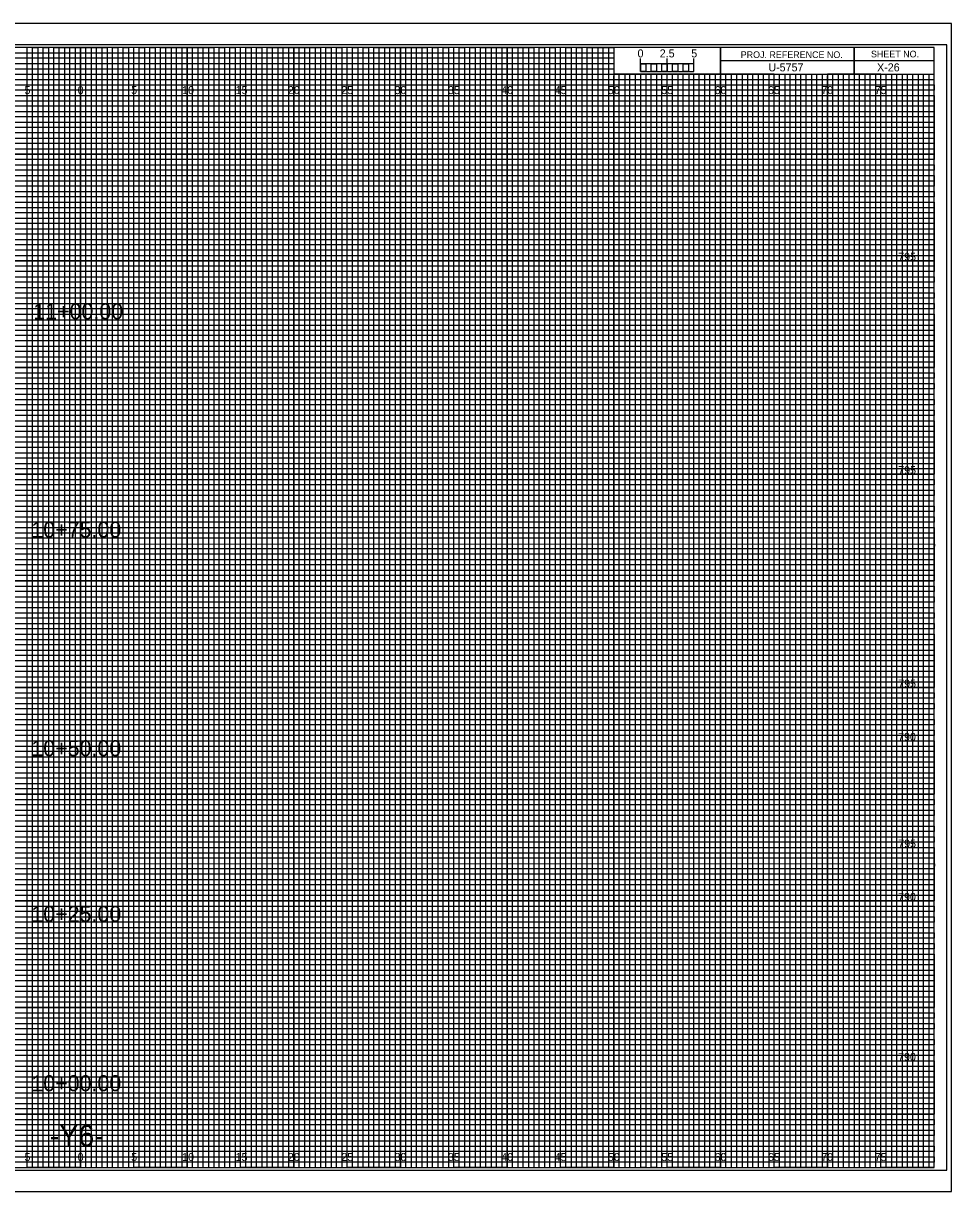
# Model space of a CAD drawing. Extents: x -7 to 162, y -2 to 107.
# Drawn here: x 74.6 to 161.7, y -2.3 to 107.3 of the extents above; entities that cross this region are included whole.
import ezdxf

# ---------------------------------------------------------------- set-up
doc = ezdxf.new("R2010")
doc.units = 0
for name, color, linetype in [('Exist Cross Section Cell', 7, 'Continuous'), ('Exist XS Center Line Elevation Label', 7, 'Continuous'), ('Prop CMT Pvmt Surface Shoulder', 7, 'Continuous'), ('Prop CMT Shld Paved Course 1', 7, 'Continuous'), ('Prop CMT Shld Paved Course 2', 7, 'Continuous'), ('Prop CMT Shld Paved Course 3', 7, 'Continuous'), ('Prop XS Alignment Label', 7, 'Continuous'), ('Prop XS Bar Scale Labels', 7, 'Continuous'), ('Prop XS Elevation Labels', 7, 'Continuous'), ('Prop XS Finish Grade CurbGutter', 7, 'Continuous'), ('Prop XS Hydro Elevations', 7, 'Continuous'), ('Prop XS Project Number', 7, 'Continuous'), ('Prop XS SE Text', 7, 'Continuous'), ('Prop XS Sheet Number', 7, 'Continuous'), ('Prop XS Side Slope Text', 7, 'Continuous'), ('Prop XS Station Labels', 7, 'Continuous'), ('Sheet DOT Grid CELL', 7, 'Continuous')]:
    doc.layers.add(name, color=color, linetype=linetype)

msp = doc.modelspace()

# ---------------------------------------------------------------- linework, layer by layer
at = {"layer": 'Exist Cross Section Cell'}
for p, q in [((75, 105), (70, 105)), ((75, 0), (75, 105)), ((85, 105), (80, 105)), ((80, 105), (80, 0)), ((85, 0), (85, 105)), ((95, 105), (90, 105)), ((90, 105), (90, 0)), ((95, 0), (95, 105)), ((105, 105), (100, 105)), ((100, 105), (100, 0)), ((105, 0), (105, 105)), ((115, 105), (110, 105)), ((110, 105), (110, 0)), ((115, 0), (115, 105)), ((125, 105), (120, 105)), ((120, 105), (120, 0)), ((125, 0), (125, 105)), ((130, 105), (130, 0)), ((135, 0), (135, 102.5)), ((145, 102.5), (140, 102.5)), ((140, 102.5), (140, 0)), ((145, 0), (145, 102.5)), ((155, 102.5), (150, 102.5)), ((150, 102.5), (150, 0)), ((155, 0), (155, 102.5)), ((80, 0), (75, 0)), ((90, 0), (85, 0)), ((100, 0), (95, 0)), ((110, 0), (105, 0)), ((120, 0), (115, 0)), ((130, 0), (125, 0)), ((140, 0), (135, 0)), ((150, 0), (145, 0)), ((160, 0), (155, 0)), ((160, 0), (160, 0))]:
    msp.add_line(p, q, dxfattribs=at)
for points in [[(0, 100), (160, 100), (160, 95), (0, 95)], [(0, 90), (160, 90), (160, 85), (0, 85)], [(0, 80), (160, 80), (160, 75), (0, 75)], [(0, 70), (160, 70), (160, 65), (0, 65)], [(0, 60), (160, 60), (160, 55), (0, 55)], [(0, 50), (160, 50), (160, 45), (0, 45)], [(0, 40), (160, 40), (160, 35), (0, 35)], [(0, 30), (160, 30), (160, 25), (0, 25)], [(0, 20), (160, 20), (160, 15), (0, 15)], [(0, 10), (160, 10), (160, 5), (0, 5)]]:
    msp.add_lwpolyline(points, dxfattribs=at)
at = {"layer": 'Exist XS Center Line Elevation Label'}
for points in [[(72.5, 0), (77.5, 0), (77.5, 105), (82.5, 105), (82.5, 0), (87.5, 0), (87.5, 105), (92.5, 105), (92.5, 0), (97.5, 0), (97.5, 105), (102.5, 105), (102.5, 0), (107.5, 0), (107.5, 105), (112.5, 105), (112.5, 0), (117.5, 0), (117.5, 105), (122.5, 105), (122.5, 0), (127.5, 0), (127.5, 105), (129.97, 105), (130, 105), (130, 102.5), (132.5, 102.5), (132.5, 0), (137.5, 0), (137.5, 102.5), (142.5, 102.5), (142.5, 0), (147.5, 0), (147.5, 102.5), (152.5, 102.5), (152.5, 0), (157.5, 0), (157.5, 102.5)], [(0, 102.5), (137.5, 102.5)], [(0, 92.5), (160, 92.5), (160, 97.5), (0, 97.5)], [(0, 82.5), (160, 82.5), (160, 87.5), (0, 87.5)], [(0, 72.5), (160, 72.5), (160, 77.5), (0, 77.5)], [(0, 62.5), (160, 62.5), (160, 67.5), (0, 67.5)], [(0, 52.5), (160, 52.5), (160, 57.5), (0, 57.5)], [(0, 42.5), (160, 42.5), (160, 47.5), (0, 47.5)], [(0, 32.5), (160, 32.5), (160, 37.5), (0, 37.5)], [(0, 22.5), (160, 22.5), (160, 27.5), (0, 27.5)], [(0, 12.5), (160, 12.5), (160, 17.5), (0, 17.5)], [(0, 2.5), (160, 2.5), (160, 7.5), (0, 7.5)]]:
    msp.add_lwpolyline(points, dxfattribs=at)
at = {"layer": 'Prop CMT Pvmt Surface Shoulder'}
msp.add_lwpolyline([(-5.4, -0.25), (161.2, -0.25), (161.2, 105.25), (-5.4, 105.25)], close=True, dxfattribs=at)
at = {"layer": 'Prop CMT Shld Paved Course 1'}
for p, q in [((133.5, 102.5), (133, 102.5)), ((133, 102.5), (133, 0)), ((133.5, 0), (133.5, 102.5)), ((134.5, 102.5), (134, 102.5)), ((134, 102.5), (134, 0)), ((134.5, 0), (134.5, 102.5)), ((133, 0), (132.5, 0)), ((134, 0), (133.5, 0))]:
    msp.add_line(p, q, dxfattribs=at)
for points in [[(75, 0), (75.5, 0), (75.5, 105), (76, 105), (76, 0)], [(76, 0), (76.5, 0), (76.5, 105), (77, 105), (77, 0)], [(77.5, 0), (78, 0), (78, 105), (78.5, 105), (78.5, 0)], [(78.5, 0), (79, 0), (79, 105), (79.5, 105), (79.5, 0)], [(80, 0), (80.5, 0), (80.5, 105), (81, 105), (81, 0)], [(81, 0), (81.5, 0), (81.5, 105), (82, 105), (82, 0)], [(82.5, 0), (83, 0), (83, 105), (83.5, 105), (83.5, 0)], [(83.5, 0), (84, 0), (84, 105), (84.5, 105), (84.5, 0)], [(85, 0), (85.5, 0), (85.5, 105), (86, 105), (86, 0)], [(86, 0), (86.5, 0), (86.5, 105), (87, 105), (87, 0)], [(87.5, 0), (88, 0), (88, 105), (88.5, 105), (88.5, 0)], [(88.5, 0), (89, 0), (89, 105), (89.5, 105), (89.5, 0)], [(90, 0), (90.5, 0), (90.5, 105), (91, 105), (91, 0)], [(91, 0), (91.5, 0), (91.5, 105), (92, 105), (92, 0)], [(92.5, 0), (93, 0), (93, 105), (93.5, 105), (93.5, 0)], [(93.5, 0), (94, 0), (94, 105), (94.5, 105), (94.5, 0)], [(95, 0), (95.5, 0), (95.5, 105), (96, 105), (96, 0)], [(96, 0), (96.5, 0), (96.5, 105), (97, 105), (97, 0)], [(97.5, 0), (98, 0), (98, 105), (98.5, 105), (98.5, 0)], [(98.5, 0), (99, 0), (99, 105), (99.5, 105), (99.5, 0)], [(100, 0), (100.5, 0), (100.5, 105), (101, 105), (101, 0)], [(101, 0), (101.5, 0), (101.5, 105), (102, 105), (102, 0)], [(102.5, 0), (103, 0), (103, 105), (103.5, 105), (103.5, 0)], [(103.5, 0), (104, 0), (104, 105), (104.5, 105), (104.5, 0)], [(105, 0), (105.5, 0), (105.5, 105), (106, 105), (106, 0)], [(106, 0), (106.5, 0), (106.5, 105), (107, 105), (107, 0)], [(107.5, 0), (108, 0), (108, 105), (108.5, 105), (108.5, 0)], [(108.5, 0), (109, 0), (109, 105), (109.5, 105), (109.5, 0)], [(110, 0), (110.5, 0), (110.5, 105), (111, 105), (111, 0)], [(111, 0), (111.5, 0), (111.5, 105), (112, 105), (112, 0)], [(112.5, 0), (113, 0), (113, 105), (113.5, 105), (113.5, 0)], [(113.5, 0), (114, 0), (114, 105), (114.5, 105), (114.5, 0)], [(115, 0), (115.5, 0), (115.5, 105), (116, 105), (116, 0)], [(116, 0), (116.5, 0), (116.5, 105), (117, 105), (117, 0)], [(117.5, 0), (118, 0), (118, 105), (118.5, 105), (118.5, 0)], [(118.5, 0), (119, 0), (119, 105), (119.5, 105), (119.5, 0)], [(120, 0), (120.5, 0), (120.5, 105), (121, 105), (121, 0)], [(121, 0), (121.5, 0), (121.5, 105), (122, 105), (122, 0)], [(122.5, 0), (123, 0), (123, 105), (123.5, 105), (123.5, 0)], [(123.5, 0), (124, 0), (124, 105), (124.5, 105), (124.5, 0)], [(125, 0), (125.5, 0), (125.5, 105), (126, 105), (126, 0)], [(126, 0), (126.5, 0), (126.5, 105), (127, 105), (127, 0)], [(127.5, 0), (128, 0), (128, 105), (128.5, 105), (128.5, 0)], [(128.5, 0), (129, 0), (129, 105), (129.5, 105), (129.5, 0)], [(130, 0), (130.5, 0), (130.5, 102.5), (131.01, 102.5), (131.01, 0)], [(131, 0), (131.5, 0), (131.5, 102.5), (132, 102.5), (132, 0)], [(135, 0), (135.49, 0), (135.49, 102.5), (136, 102.5), (136, 0)], [(136, 0), (136.5, 0), (136.5, 102.5), (137.03, 102.5), (137.03, 0)], [(137.5, 0), (138, 0), (138, 102.5), (138.5, 102.5), (138.5, 0)], [(138.5, 0), (139, 0), (139, 102.5), (139.5, 102.5), (139.5, 0)], [(140, 0), (140.5, 0), (140.5, 102.5), (141, 102.5), (141, 0)], [(141, 0), (141.5, 0), (141.5, 102.5), (142, 102.5), (142, 0)], [(142.5, 0), (143, 0), (143, 102.5), (143.5, 102.5), (143.5, 0)], [(143.5, 0), (144, 0), (144, 102.5), (144.5, 102.5), (144.5, 0)], [(145, 0), (145.5, 0), (145.5, 102.5), (146, 102.5), (146, 0)], [(146, 0), (146.5, 0), (146.5, 102.5), (147, 102.5), (147, 0)], [(147.5, 0), (148, 0), (148, 102.5), (148.5, 102.5), (148.5, 0)], [(148.5, 0), (149, 0), (149, 102.5), (149.5, 102.5), (149.5, 0)], [(150, 0), (150.5, 0), (150.5, 102.5), (151, 102.5), (151, 0)], [(151, 0), (151.5, 0), (151.5, 102.5), (152, 102.5), (152, 0)], [(152.5, 0), (153, 0), (153, 102.5), (153.5, 102.5), (153.5, 0)], [(153.5, 0), (154, 0), (154, 102.5), (154.5, 102.5), (154.5, 0)], [(155, 0), (155.5, 0), (155.5, 102.5), (156, 102.5), (156, 0)], [(156, 0), (156.5, 0), (156.5, 102.5), (157, 102.5), (157, 0)], [(157.5, 0), (158, 0), (158, 102.5), (158.5, 102.5), (158.5, 0)], [(158.5, 0), (159, 0), (159, 102.5), (159.5, 102.5), (159.5, 0)]]:
    msp.add_lwpolyline(points, dxfattribs=at)
at = {"layer": 'Prop CMT Shld Paved Course 2'}
for p, q in [((132.5, 102.75), (132.5, 103.95)), ((132.5, 103.45), (132.5, 103.95)), ((135, 102.75), (135, 103.95)), ((137.5, 102.75), (137.5, 103.95)), ((137.5, 103.45), (137.5, 103.95))]:
    msp.add_line(p, q, dxfattribs=at)
for points in [[(137.5, 103.45), (132.5, 103.45), (132.5, 102.75), (137.5, 102.75)], [(132.5, 103.45), (133, 103.45), (133, 102.75), (132.5, 102.75)], [(133.5, 103.45), (134, 103.45), (134, 102.75), (133.5, 102.75)], [(134.5, 103.45), (135, 103.45), (135, 102.75), (134.5, 102.75)], [(135.5, 103.45), (136, 103.45), (136, 102.75), (135.5, 102.75)], [(136.5, 103.45), (137, 103.45), (137, 102.75), (136.5, 102.75)]]:
    msp.add_lwpolyline(points, close=True, dxfattribs=at)
at = {"layer": 'Prop CMT Shld Paved Course 3'}
msp.add_lwpolyline([(-6.7, -2.25), (161.65, -2.25), (161.65, 107.25), (-6.7, 107.25)], close=True, dxfattribs=at)
at = {"layer": 'Prop XS Finish Grade CurbGutter'}
for p, q in [((161.65, 107.25), (-6.7, 107.25)), ((-6.7, -2.25), (161.65, -2.25))]:
    msp.add_line(p, q, dxfattribs=at)
at = {"layer": 'Prop XS Hydro Elevations'}
for p, q in [((152.5, 105), (152.5, 102.5)), ((152.5, 102.5), (152.5, 105)), ((160, 103.75), (140, 103.75)), ((140, 103.75), (140, 102.5)), ((140, 102.5), (160, 102.5))]:
    msp.add_line(p, q, dxfattribs=at)
for points in [[(160, 105), (0, 105), (0, 0), (160, 0)], [(140, 105), (130, 105), (130, 102.52), (140, 102.52)], [(160, 105), (140, 105), (140, 102.5), (160, 102.5)]]:
    msp.add_lwpolyline(points, close=True, dxfattribs=at)
at = {"layer": 'Prop XS Side Slope Text'}
for p, q in [((0, 104.5), (130, 104.5)), ((130, 104.5), (130, 103.99)), ((130, 103.99), (0, 103.99)), ((0, 103.5), (130, 103.5)), ((130, 102.95), (0, 102.95)), ((130, 103.5), (130, 102.95)), ((0, 102), (160, 102))]:
    msp.add_line(p, q, dxfattribs=at)
for points in [[(0, 101.5), (135, 101.5), (160, 101.5), (160, 101), (0, 101)], [(0, 100.5), (160, 100.5), (160, 99.5), (0, 99.5)], [(0, 99), (160, 99), (160, 98.5), (0, 98.49)], [(0, 98), (160, 98), (160, 97), (0, 97)], [(0, 96.5), (160, 96.5), (160, 96), (0, 96)], [(0, 95.5), (160, 95.5), (160, 94.5), (0, 94.5)], [(0, 94), (160, 94), (160, 93.5), (0, 93.5)], [(0, 93), (160, 93), (160, 92), (0, 92)], [(0, 91.5), (160, 91.5), (160, 91), (0, 91)], [(0, 90.5), (160, 90.5), (160, 89.5), (0, 89.5)], [(0, 89), (160, 89), (160, 88.5), (0, 88.5)], [(0, 88), (160, 88), (160, 86.98), (160, 86.5), (160, 86), (0, 86)], [(0, 87), (160, 87), (160, 86.5), (0, 86.5)], [(0, 85.5), (160, 85.5), (160, 84.5), (0, 84.52)], [(0, 84.52), (160, 84.5), (160, 84), (0, 84)], [(0, 83.5), (160, 83.5), (160, 83), (0, 83)], [(0, 82), (160, 82), (160, 81.5), (0, 81.5)], [(0, 81), (160, 81), (160, 80.5), (0, 80.5)], [(-0.04, 79.45), (160, 79.45), (160, 78.94), (-0.04, 78.94)], [(0, 78.5), (160, 78.5), (160, 78), (0, 78)], [(0, 77), (160, 77), (160, 76.5), (0, 76.5)], [(0, 76), (160, 76), (160, 75.5), (0, 75.5)], [(0, 74.5), (160, 74.5), (160, 74), (0, 74)], [(0, 73.5), (160, 73.5), (160, 73), (0, 73)], [(0, 72), (160, 72), (160, 71.5), (0, 71.5)], [(0, 71), (160, 71), (160, 70.5), (0, 70.5)], [(0, 69.5), (160, 69.5), (160, 68.99), (0, 69)], [(0, 68.5), (160, 68.5), (160, 68), (0, 68)], [(0, 67), (160, 67), (160, 66.5), (0, 66.5)], [(0, 66), (160, 66), (160, 65.5), (0, 65.5)], [(0, 64.5), (160, 64.5), (160, 64), (0, 64)], [(0, 63.5), (160, 63.5), (160, 63), (0, 63)], [(0, 62), (160, 62), (160, 61.5), (0, 61.5)], [(0, 61), (160, 61), (160, 60.5), (0, 60.5)], [(0, 59.5), (160, 59.5), (160, 59), (0, 59)], [(0, 58.5), (160.03, 58.45), (160, 58), (0, 58)], [(0, 57), (160, 57), (160, 56.5), (0, 56.5)], [(0, 56), (160, 56), (160, 55.5), (0, 55.5)], [(0, 54.5), (160, 54.5), (160, 54), (0, 54)], [(0, 53.5), (160, 53.5), (160, 53), (0, 53)], [(0, 52), (160, 52), (160, 51.5), (0, 51.5)], [(0, 51), (160, 51), (160, 50.5), (0, 50.5)], [(0, 49.5), (160, 49.5), (160, 49), (0, 49)], [(0, 48.5), (160, 48.5), (160, 48), (0, 48)], [(0, 47), (160, 47), (160, 46.5), (0, 46.5)], [(0, 46), (160, 46), (160, 45.5), (0, 45.5)], [(0, 44.5), (160, 44.5), (160, 44), (0, 44)], [(0, 43.5), (160, 43.5), (160, 43), (0, 43)], [(0, 42), (160, 42), (160, 41.5), (0, 41.5)], [(0, 41), (160, 41), (160, 40.5), (0, 40.5)], [(0, 39.5), (160, 39.5), (160, 38.99), (0, 39)], [(0, 38.5), (160, 38.5), (160, 38), (0, 38)], [(0, 37), (160, 37), (160, 36.5), (0, 36.5)], [(0, 36), (160, 36), (160, 35.5), (0, 35.5)], [(0, 34.5), (160, 34.5), (160, 34), (0, 34)], [(0, 33.5), (160, 33.5), (160, 33), (0, 33)], [(0, 32), (160, 32), (160, 31.5), (0, 31.5)], [(0, 31), (160, 31), (160, 30.5), (0, 30.5)], [(0, 29.5), (160, 29.5), (160, 29), (0, 29)], [(0, 28.5), (160.03, 28.46), (160, 28), (0, 28)], [(0, 27), (160, 27), (160, 26.5), (0, 26.5)], [(0, 26), (160, 26), (160, 25.5), (0, 25.5)], [(0, 24.5), (160, 24.5), (160, 24), (0, 24)], [(0, 23.5), (160, 23.5), (160, 23), (0, 23)], [(0, 22), (160, 22), (160, 21.5), (0, 21.5)], [(0, 21), (160, 21), (160, 20.5), (0, 20.5)], [(0, 19.5), (160, 19.5), (160, 19), (0, 19)], [(0, 18.5), (160, 18.5), (160, 18), (0, 18)], [(0, 17), (160, 17), (160, 16.5), (0, 16.5)], [(0, 16), (160, 16), (160, 15.5), (0, 15.5)], [(0, 14.5), (160, 14.5), (160, 14), (0, 14)], [(0, 13.5), (160, 13.5), (160, 13), (0, 13)], [(0, 12), (160, 12), (160, 11.5), (0, 11.5)], [(0, 11), (160, 11), (160, 10.5), (0, 10.5)], [(0, 9.5), (160, 9.5), (160, 9), (0, 9)], [(0, 8.5), (160, 8.5), (160, 8), (0, 8)], [(0, 7), (160, 7), (160, 6.5), (0, 6.5)], [(0, 6), (160, 6), (160, 5.5), (0, 5.5)], [(0, 4.5), (160, 4.5), (160, 4), (0, 4)], [(0, 3.5), (160, 3.5), (160, 3), (0, 3)], [(0, 2), (160, 2), (160, 1.5), (0, 1.5)], [(0, 1), (160, 1), (160, 0.5), (0, 0.5)]]:
    msp.add_lwpolyline(points, dxfattribs=at)
at = {"layer": 'Sheet DOT Grid CELL'}
for p, q in [((75, 0), (75, 105)), ((80, 0), (80, 105)), ((85, 0), (85, 105)), ((90, 0), (90, 105)), ((95, 0), (95, 105)), ((100, 0), (100, 105)), ((105, 0), (105, 105)), ((110, 0), (110, 105)), ((115, 0), (115, 105)), ((120, 0), (120, 105)), ((125, 0), (125, 105)), ((130, 0), (130, 102.34)), ((135, 0), (135, 102.34)), ((140, 0), (140, 102.34)), ((145, 0), (145, 102.34)), ((150, 0), (150, 102.34)), ((155, 0), (155, 102.34)), ((0, 100), (160, 100)), ((0, 95), (160, 95)), ((0, 90), (160, 90)), ((0, 85), (160, 85)), ((0, 80), (160, 80)), ((0, 75), (160, 75)), ((0, 70), (160, 70)), ((0, 65), (160, 65)), ((0, 60), (160, 60)), ((0, 55), (160, 55)), ((0, 50), (160, 50)), ((0, 45), (160, 45)), ((0, 40), (160, 40)), ((0, 35), (160, 35)), ((0, 30), (160, 30)), ((0, 25), (160, 25)), ((0, 20), (160, 20)), ((0, 15), (160, 15)), ((0, 10), (160, 10)), ((0, 5), (160, 5))]:
    msp.add_line(p, q, dxfattribs=at)

# ---------------------------------------------------------------- texts
at = {"layer": 'Prop CMT Shld Paved Course 2'}
msp.add_text('0', height=0.75, dxfattribs=at).set_placement((132.21, 104.06))
at = {"layer": 'Prop XS Alignment Label'}
msp.add_text('-Y6-', height=2, dxfattribs=at).set_placement((77.12, 2))
at = {"layer": 'Prop XS Bar Scale Labels'}
for s, p in [('2.5', (134.29, 104.06)), ('5', (137.24, 104.06))]:
    msp.add_text(s, height=0.75, dxfattribs=at).set_placement(p)
at = {"layer": 'Prop XS Elevation Labels'}
for s, p in [('795', (156.64, 85)), ('795', (156.64, 65)), ('795', (156.64, 45)), ('790', (156.63, 40)), ('795', (156.64, 30)), ('790', (156.63, 25)), ('790', (156.63, 10))]:
    msp.add_text(s, height=0.75, dxfattribs=at).set_placement(p)
at = {"layer": 'Prop XS Hydro Elevations'}
for s, p in [('PROJ. REFERENCE NO.', (141.88, 104)), ('SHEET NO.', (154.09, 104.06))]:
    msp.add_text(s, height=0.625, dxfattribs=at).set_placement(p)
at = {"layer": 'Prop XS Project Number'}
msp.add_text('U-5757', height=0.75, dxfattribs=at).set_placement((144.47, 102.75))
at = {"layer": 'Prop XS SE Text'}
for s, p in [('5', (74.74, 100.62)), ('0', (79.73, 100.62)), ('0', (79.73, 100.62)), ('5', (84.74, 100.62)), ('10', (89.52, 100.62)), ('15', (94.53, 100.62)), ('20', (99.43, 100.62)), ('25', (104.44, 100.62)), ('30', (109.43, 100.62)), ('35', (114.44, 100.62)), ('40', (119.43, 100.62)), ('45', (124.44, 100.62)), ('50', (129.43, 100.62)), ('55', (134.44, 100.62)), ('60', (139.43, 100.62)), ('65', (144.44, 100.62)), ('70', (149.43, 100.62)), ('75', (154.44, 100.62)), ('5', (74.74, 0.62)), ('0', (79.73, 0.62)), ('0', (79.73, 0.62)), ('5', (84.74, 0.62)), ('10', (89.52, 0.62)), ('15', (94.53, 0.62)), ('20', (99.43, 0.62)), ('25', (104.44, 0.62)), ('30', (109.43, 0.62)), ('35', (114.44, 0.62)), ('40', (119.43, 0.62)), ('45', (124.44, 0.62)), ('50', (129.43, 0.62)), ('55', (134.44, 0.62)), ('60', (139.43, 0.62)), ('65', (144.44, 0.62)), ('70', (149.43, 0.62)), ('75', (154.44, 0.62))]:
    msp.add_text(s, height=0.75, dxfattribs=at).set_placement(p)
at = {"layer": 'Prop XS Sheet Number'}
msp.add_text('X-26', height=0.75, dxfattribs=at).set_placement((154.66, 102.75))
at = {"layer": 'Prop XS Station Labels'}
for s, p in [('11+00.00', (75.57, 79.51)), ('10+75.00', (75.39, 59.05)), ('10+50.00', (75.39, 38.56)), ('10+25.00', (75.39, 23.03)), ('10+00.00', (75.39, 7.16))]:
    msp.add_text(s, height=1.5, dxfattribs=at).set_placement(p)

doc.saveas('drawing.dxf')
